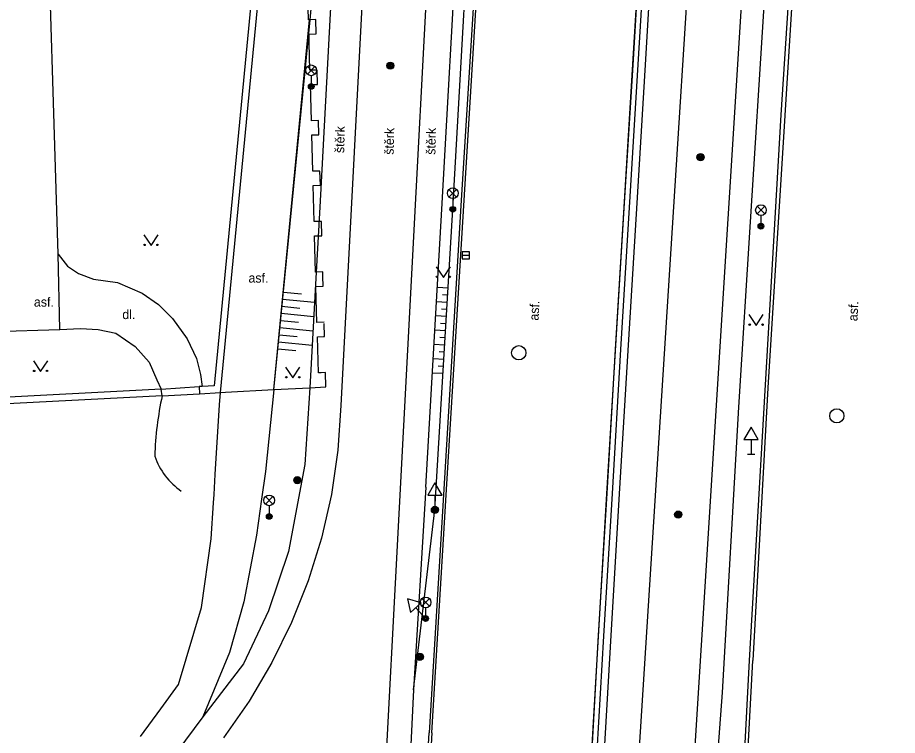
# Model space of a CAD drawing. Extents: x -599951 to -598963, y -1164095 to -1162939.
# Drawn here: x -599224.4 to -599162.9, y -1163976.7 to -1163926.5 of the extents above; entities that cross this region are included whole.
import ezdxf

# ---------------------------------------------------------------- set-up
doc = ezdxf.new("R2010")
doc.units = 0
for name, color, linetype in [('Level 1', 7, 'Continuous'), ('Level 10', 7, 'Continuous'), ('Level 11', 7, 'Continuous'), ('Level 13', 7, 'Continuous'), ('Level 14', 7, 'Continuous'), ('Level 15', 7, 'Continuous'), ('Level 25', 7, 'Continuous'), ('Level 27', 7, 'Continuous'), ('Level 33', 7, 'Continuous'), ('Level 34', 7, 'Continuous'), ('Level 36', 7, 'Continuous'), ('Level 40', 7, 'Continuous'), ('Level 54', 7, 'Continuous'), ('Level 7', 7, 'Continuous'), ('Level 8', 7, 'Continuous'), ('Level 9', 7, 'Continuous')]:
    doc.layers.add(name, color=color, linetype=linetype)

msp = doc.modelspace()

# ---------------------------------------------------------------- linework, layer by layer
at = {"layer": 'Level 1'}
for points in [[(-599203.06, -1163944.58), (-599203.07, -1163944.25), (-599203.57, -1163944.26), (-599203.64, -1163941.73), (-599203.14, -1163941.72), (-599203.17, -1163940.72), (-599203.67, -1163940.73), (-599203.74, -1163938.2), (-599203.24, -1163938.19), (-599203.27, -1163937.19), (-599203.77, -1163937.2), (-599203.84, -1163934.67), (-599203.34, -1163934.66), (-599203.37, -1163933.66), (-599203.87, -1163933.67), (-599203.94, -1163931.14), (-599203.44, -1163931.13), (-599203.47, -1163930.13), (-599203.97, -1163930.14), (-599204.02, -1163928.22), (-599204.02, -1163928.14), (-599204.03, -1163927.61), (-599203.53, -1163927.6), (-599203.56, -1163926.6), (-599204, -1163926.62), (-599204.06, -1163926.62), (-599204.13, -1163924.09)], [(-599203.06, -1163944.58), (-599203.07, -1163944.25), (-599203.57, -1163944.26), (-599203.64, -1163941.73), (-599203.14, -1163941.72), (-599203.17, -1163940.72), (-599203.67, -1163940.73), (-599203.74, -1163938.2), (-599203.24, -1163938.19), (-599203.27, -1163937.19), (-599203.77, -1163937.2), (-599203.84, -1163934.67), (-599203.34, -1163934.66), (-599203.37, -1163933.66), (-599203.87, -1163933.67), (-599203.94, -1163931.14), (-599203.44, -1163931.13), (-599203.47, -1163930.13), (-599203.97, -1163930.14), (-599204.02, -1163928.22), (-599204.02, -1163928.14), (-599204.03, -1163927.61), (-599203.53, -1163927.6), (-599203.56, -1163926.6), (-599204, -1163926.62), (-599204.06, -1163926.62), (-599204.13, -1163924.09)], [(-599202.97, -1163947.77), (-599202.98, -1163947.77), (-599203.48, -1163947.79), (-599203.55, -1163945.26), (-599203.05, -1163945.25), (-599203.06, -1163944.58)], [(-599202.97, -1163947.77), (-599202.98, -1163947.77), (-599203.48, -1163947.79), (-599203.55, -1163945.26), (-599203.05, -1163945.25), (-599203.06, -1163944.58)], [(-599210.23, -1163952.69), (-599209.89, -1163952.67), (-599206.5, -1163952.47), (-599203.97, -1163952.36), (-599203.23, -1163952.32), (-599202.85, -1163952.3), (-599202.88, -1163951.3), (-599203.18, -1163951.31), (-599203.38, -1163951.32), (-599203.45, -1163948.79), (-599203.03, -1163948.77), (-599202.95, -1163948.77), (-599202.98, -1163947.86)], [(-599210.23, -1163952.69), (-599209.89, -1163952.67), (-599206.5, -1163952.47), (-599203.97, -1163952.36), (-599203.23, -1163952.32), (-599202.85, -1163952.3), (-599202.88, -1163951.3), (-599203.18, -1163951.31), (-599203.38, -1163951.32), (-599203.45, -1163948.79), (-599203.03, -1163948.77), (-599202.95, -1163948.77), (-599202.98, -1163947.86)], [(-599214.31, -1163952.91), (-599211.69, -1163952.77)]]:
    msp.add_lwpolyline(points, dxfattribs=at)
at = {"layer": 'Level 10'}
for points in [[(-599162.85, -1163820.04), (-599165.66, -1163854.88), (-599168.46, -1163894.41), (-599171.02, -1163933.26), (-599173.23, -1163971.43)], [(-599162.85, -1163820.04), (-599165.66, -1163854.88), (-599168.46, -1163894.41), (-599171.02, -1163933.26), (-599173.23, -1163971.43)], [(-599189.93, -1163884.08), (-599190.81, -1163898.12), (-599192.15, -1163919.43), (-599193.42, -1163940)], [(-599193.42, -1163940), (-599194.6, -1163959.46), (-599195.62, -1163976.51)], [(-599173.23, -1163971.43), (-599174.29, -1163991.9), (-599175.35, -1164011.75), (-599176.55, -1164033.54), (-599177.56, -1164051.44), (-599178.64, -1164071.21)], [(-599196.92, -1163999.13), (-599195.62, -1163976.51)]]:
    msp.add_lwpolyline(points, dxfattribs=at)
at = {"layer": 'Level 11'}
for points in [[(-599172.9, -1163813.11), (-599173.38, -1163820.1), (-599174.07, -1163830.07), (-599174.74, -1163840.04), (-599175.4, -1163850), (-599175.95, -1163858.03), (-599176.47, -1163865.91), (-599177.1, -1163875.95), (-599177.75, -1163885.93), (-599178.52, -1163897.89), (-599179.3, -1163909.98), (-599179.92, -1163919.81), (-599180.51, -1163929.76), (-599181.12, -1163939.81), (-599181.72, -1163949.74), (-599182.32, -1163959.77), (-599182.91, -1163969.7), (-599183.49, -1163979.74), (-599184.17, -1163991.77), (-599185.17, -1164009.07), (-599185.26, -1164010.75)], [(-599172.9, -1163813.11), (-599173.38, -1163820.1), (-599174.07, -1163830.07), (-599174.74, -1163840.04), (-599175.4, -1163850), (-599175.95, -1163858.03), (-599176.47, -1163865.91), (-599177.1, -1163875.95), (-599177.75, -1163885.93), (-599178.52, -1163897.89), (-599179.3, -1163909.98), (-599179.92, -1163919.81), (-599180.51, -1163929.76), (-599181.12, -1163939.81), (-599181.72, -1163949.74), (-599182.32, -1163959.77), (-599182.91, -1163969.7), (-599183.49, -1163979.74), (-599184.17, -1163991.77), (-599185.17, -1164009.07), (-599185.26, -1164010.75)], [(-599197.62, -1163823.43), (-599198.25, -1163843.69), (-599199.2, -1163863.95), (-599200.91, -1163896.76), (-599202.16, -1163918.73), (-599203.28, -1163939.73), (-599203.53, -1163944.26), (-599203.97, -1163952.36)], [(-599197.62, -1163823.43), (-599198.25, -1163843.69), (-599199.2, -1163863.95), (-599200.91, -1163896.76), (-599202.16, -1163918.73), (-599203.28, -1163939.73), (-599203.53, -1163944.26), (-599203.97, -1163952.36)], [(-599195.85, -1163959.31), (-599194.73, -1163939.87), (-599193.59, -1163919.49), (-599192.41, -1163897.89), (-599191.62, -1163883.93)], [(-599168.22, -1163894.41), (-599169.52, -1163913.85), (-599170.73, -1163933.3)], [(-599193.23, -1163939.99), (-599191.96, -1163919.44), (-599190.62, -1163898.15)], [(-599171.48, -1163913.8), (-599172.21, -1163925.63), (-599173.16, -1163940.74), (-599173.97, -1163953.72)], [(-599186.16, -1164011.52), (-599186, -1164008.75), (-599185.03, -1163991.47), (-599184.35, -1163979.77), (-599183.76, -1163969.76), (-599183.18, -1163959.77), (-599182.58, -1163949.77), (-599181.98, -1163939.79), (-599181.35, -1163929.78), (-599180.76, -1163919.85), (-599180.56, -1163916.59)], [(-599206.5, -1163952.47), (-599204, -1163926.62)], [(-599170.73, -1163933.3), (-599171.92, -1163952.37), (-599172.98, -1163971.45)], [(-599195.43, -1163976.51), (-599194.4, -1163959.47), (-599193.23, -1163939.99)], [(-599221.47, -1163948.29), (-599221.59, -1163943.02)], [(-599221.59, -1163943.02), (-599220.94, -1163943.84), (-599220.17, -1163944.35), (-599219.12, -1163944.75), (-599217.44, -1163945), (-599215.7, -1163945.73), (-599214.57, -1163946.53), (-599213.59, -1163947.51), (-599212.57, -1163948.93), (-599211.91, -1163950.32), (-599211.62, -1163951.44), (-599211.51, -1163952.26)], [(-599221.47, -1163948.29), (-599220.03, -1163948.2), (-599218.79, -1163948.28), (-599217.55, -1163948.53), (-599216.21, -1163949.48), (-599215.22, -1163950.57), (-599214.68, -1163951.81), (-599214.37, -1163952.46)], [(-599226.09, -1163948.43), (-599221.47, -1163948.29)], [(-599203.97, -1163952.36), (-599204.33, -1163957.73), (-599205.47, -1163963.81), (-599206.88, -1163967.96), (-599208.62, -1163971.68), (-599211.47, -1163975.39)], [(-599203.97, -1163952.36), (-599204.33, -1163957.73), (-599205.47, -1163963.81), (-599206.88, -1163967.96), (-599208.62, -1163971.68), (-599211.47, -1163975.39)], [(-599206.5, -1163952.47), (-599206.5, -1163952.5), (-599207.07, -1163958.22), (-599207.35, -1163960.16), (-599207.71, -1163962.67), (-599208.59, -1163967.34), (-599209.61, -1163970.87), (-599211.47, -1163975.39)], [(-599206.5, -1163952.47), (-599206.5, -1163952.5), (-599207.07, -1163958.22), (-599207.35, -1163960.16), (-599207.71, -1163962.67), (-599208.59, -1163967.34), (-599209.61, -1163970.87), (-599211.47, -1163975.39)], [(-599215.82, -1163976.75), (-599214.4, -1163974.81), (-599213.16, -1163973.11), (-599211.56, -1163967.72), (-599210.88, -1163962.93), (-599210.72, -1163960.41), (-599210.68, -1163959.83), (-599210.59, -1163958.43), (-599210.29, -1163953.56), (-599210.23, -1163952.69)], [(-599215.82, -1163976.75), (-599214.4, -1163974.81), (-599213.16, -1163973.11), (-599211.56, -1163967.72), (-599210.88, -1163962.93), (-599210.72, -1163960.41), (-599210.68, -1163959.83), (-599210.59, -1163958.43), (-599210.29, -1163953.56), (-599210.23, -1163952.69)], [(-599173.97, -1163953.72), (-599175.11, -1163973.69), (-599176.62, -1163993.64)], [(-599195.85, -1163959.31), (-599196.72, -1163973.49)], [(-599178.38, -1164071.18), (-599177.31, -1164051.48), (-599176.3, -1164033.6), (-599175.12, -1164011.76), (-599174.06, -1163991.91), (-599172.98, -1163971.45)], [(-599196.72, -1163973.49), (-599197.56, -1163990.8), (-599198.17, -1163999.99)], [(-599211.47, -1163975.39), (-599216.86, -1163982.64), (-599230.24, -1164000.07), (-599257.58, -1164035.67), (-599261.16, -1164041.12), (-599262.87, -1164045.41), (-599264.04, -1164049.93), (-599264.28, -1164054.68), (-599263.81, -1164059.27), (-599262.56, -1164063.71), (-599259.99, -1164068.39), (-599256.72, -1164072.83), (-599254.73, -1164074.44)], [(-599195.43, -1163976.51), (-599196.69, -1163998.47)]]:
    msp.add_lwpolyline(points, dxfattribs=at)
for centre, radius, start, end in [((-599191.338, -1163957.881), 23.503, 167.7899, 178.19352), ((-599210.143, -1163955.513), 4.961, 199.14564, 235.26471)]:
    msp.add_arc(centre, radius, start, end, dxfattribs=at)
at = {"layer": 'Level 13'}
for points in [[(-599178.43, -1164000.2), (-599167.24, -1163821.2)], [(-599173.6, -1163862.17), (-599182.35, -1163999.95)], [(-599193.21, -1163875.57), (-599199.31, -1163990.76)], [(-599199.93, -1163918.11), (-599201.8, -1163953.59)], [(-599201.8, -1163953.59), (-599202.01, -1163956.72), (-599202.47, -1163959.82), (-599203.16, -1163962.87), (-599204.09, -1163965.87), (-599205.25, -1163968.78), (-599206.63, -1163971.59), (-599208.22, -1163974.29), (-599210.02, -1163976.85)]]:
    msp.add_lwpolyline(points, dxfattribs=at)
at = {"layer": 'Level 14'}
msp.add_lwpolyline([(-599196.72, -1163973.49), (-599195.22, -1163960.9), (-599193.97, -1163939.87), (-599192.41, -1163912.27), (-599190.93, -1163884.04)], dxfattribs=at)
at = {"layer": 'Level 15'}
for points in [[(-599204.57, -1163945.8), (-599205.83, -1163945.68)], [(-599194.3, -1163945.38), (-599195.04, -1163945.34)], [(-599203.65, -1163946.4), (-599205.88, -1163946.18)], [(-599194.36, -1163946.38), (-599195.1, -1163946.34)], [(-599194.33, -1163945.88), (-599194.7, -1163945.86)], [(-599204.67, -1163946.8), (-599205.93, -1163946.68)], [(-599194.39, -1163946.88), (-599194.76, -1163946.86)], [(-599203.7, -1163947.4), (-599205.98, -1163947.17)], [(-599194.42, -1163947.38), (-599195.16, -1163947.33)], [(-599203.76, -1163948.4), (-599206.07, -1163948.17)], [(-599204.77, -1163947.79), (-599206.03, -1163947.67)], [(-599194.45, -1163947.88), (-599194.82, -1163947.85)], [(-599204.87, -1163948.79), (-599206.12, -1163948.67)], [(-599194.48, -1163948.38), (-599195.22, -1163948.33)], [(-599194.51, -1163948.87), (-599194.88, -1163948.85)], [(-599203.81, -1163949.39), (-599206.17, -1163949.16)], [(-599194.54, -1163949.37), (-599195.27, -1163949.33)], [(-599204.96, -1163949.78), (-599206.22, -1163949.66)], [(-599194.56, -1163949.87), (-599194.93, -1163949.85)], [(-599194.6, -1163950.37), (-599195.33, -1163950.33)], [(-599194.65, -1163951.37), (-599195.39, -1163951.33)], [(-599194.62, -1163950.87), (-599194.99, -1163950.85)]]:
    msp.add_lwpolyline(points, dxfattribs=at)
at = {"layer": 'Level 25'}
for centre, radius in [((-599198.34, -1163929.82), 0.25), ((-599198.34, -1163929.82), 0.2), ((-599198.34, -1163929.82), 0.15), ((-599198.34, -1163929.82), 0.1), ((-599198.34, -1163929.82), 0.05), ((-599176.63, -1163936.22), 0.25), ((-599176.63, -1163936.22), 0.2), ((-599176.63, -1163936.22), 0.15), ((-599176.63, -1163936.22), 0.1), ((-599176.63, -1163936.22), 0.05), ((-599204.85, -1163958.82), 0.25), ((-599204.85, -1163958.82), 0.2), ((-599204.85, -1163958.82), 0.15), ((-599204.85, -1163958.82), 0.1), ((-599204.85, -1163958.82), 0.05), ((-599195.22, -1163960.9), 0.25), ((-599195.22, -1163960.9), 0.2), ((-599195.22, -1163960.9), 0.15), ((-599195.22, -1163960.9), 0.1), ((-599195.22, -1163960.9), 0.05), ((-599178.19, -1163961.23), 0.25), ((-599178.19, -1163961.23), 0.2), ((-599178.19, -1163961.23), 0.15), ((-599178.19, -1163961.23), 0.1), ((-599178.19, -1163961.23), 0.05), ((-599196.27, -1163971.18), 0.25), ((-599196.27, -1163971.18), 0.2), ((-599196.27, -1163971.18), 0.15), ((-599196.27, -1163971.18), 0.1), ((-599196.27, -1163971.18), 0.05)]:
    msp.add_circle(centre, radius, dxfattribs=at)
at = {"layer": 'Level 27'}
msp.add_line((-599193.31, -1163943.09), (-599192.81, -1163943.09), dxfattribs=at)
msp.add_lwpolyline([(-599193.31, -1163943.34), (-599192.81, -1163943.34), (-599192.81, -1163942.84), (-599193.31, -1163942.84)], close=True, dxfattribs=at)
for centre in [(-599189.35, -1163949.91), (-599167.09, -1163954.32)]:
    msp.add_circle(centre, 0.5, dxfattribs=at)
at = {"layer": 'Level 33'}
for p, q in [((-599204.145, -1163930.41), (-599203.615, -1163929.88)), ((-599204.145, -1163929.88), (-599203.615, -1163930.41)), ((-599203.88, -1163930.52), (-599203.88, -1163931.27)), ((-599194.235, -1163939.01), (-599193.705, -1163938.48)), ((-599194.235, -1163938.48), (-599193.705, -1163939.01)), ((-599193.97, -1163939.12), (-599193.97, -1163939.87)), ((-599172.665, -1163940.19), (-599172.135, -1163939.66)), ((-599172.665, -1163939.66), (-599172.135, -1163940.19)), ((-599172.4, -1163940.3), (-599172.4, -1163941.05)), ((-599207.085, -1163960.5), (-599206.555, -1163959.97)), ((-599207.085, -1163959.97), (-599206.555, -1163960.5)), ((-599206.82, -1163960.61), (-599206.82, -1163961.36)), ((-599196.135, -1163967.64), (-599195.605, -1163967.11)), ((-599196.135, -1163967.11), (-599195.605, -1163967.64)), ((-599195.87, -1163967.75), (-599195.87, -1163968.5))]:
    msp.add_line(p, q, dxfattribs=at)
for centre, radius in [((-599203.88, -1163930.145), 0.375), ((-599203.88, -1163931.27), 0.2), ((-599203.88, -1163931.27), 0.145), ((-599203.88, -1163931.27), 0.0876), ((-599193.97, -1163938.745), 0.375), ((-599172.4, -1163939.925), 0.375), ((-599193.97, -1163939.87), 0.2), ((-599193.97, -1163939.87), 0.145), ((-599193.97, -1163939.87), 0.0876), ((-599172.4, -1163941.05), 0.2), ((-599172.4, -1163941.05), 0.145), ((-599172.4, -1163941.05), 0.0876), ((-599206.82, -1163960.235), 0.375), ((-599206.82, -1163961.36), 0.2), ((-599206.82, -1163961.36), 0.145), ((-599206.82, -1163961.36), 0.0876), ((-599195.87, -1163967.375), 0.375), ((-599195.87, -1163968.5), 0.2), ((-599195.87, -1163968.5), 0.145), ((-599195.87, -1163968.5), 0.0876)]:
    msp.add_circle(centre, radius, dxfattribs=at)
at = {"layer": 'Level 34'}
for p, q in [((-599173.09, -1163955.982), (-599173.09, -1163957)), ((-599173.34, -1163957), (-599172.84, -1163957)), ((-599195.22, -1163959.882), (-599195.22, -1163960.9)), ((-599195.47, -1163960.9), (-599194.97, -1163960.9)), ((-599196.56, -1163967.752), (-599195.87, -1163968.5))]:
    msp.add_line(p, q, dxfattribs=at)
for points in [[(-599173.59, -1163955.982), (-599172.59, -1163955.982), (-599173.09, -1163955.116)], [(-599195.72, -1163959.882), (-599194.72, -1163959.882), (-599195.22, -1163959.016)], [(-599196.928, -1163968.091), (-599196.193, -1163967.413), (-599197.148, -1163967.116)]]:
    msp.add_lwpolyline(points, close=True, dxfattribs=at)
at = {"layer": 'Level 36'}
for points in [[(-599215.59, -1163941.66), (-599215.09, -1163942.41), (-599214.59, -1163941.66)], [(-599195.13, -1163943.89), (-599194.63, -1163944.64), (-599194.13, -1163943.89)], [(-599173.24, -1163947.24), (-599172.74, -1163947.99), (-599172.24, -1163947.24)], [(-599223.32, -1163950.48), (-599222.82, -1163951.23), (-599222.32, -1163950.48)], [(-599205.67, -1163950.92), (-599205.17, -1163951.67), (-599204.67, -1163950.92)]]:
    msp.add_lwpolyline(points, dxfattribs=at)
for centre in [(-599215.54, -1163942.36), (-599214.641, -1163942.36), (-599195.08, -1163944.59), (-599194.181, -1163944.59), (-599173.19, -1163947.94), (-599172.291, -1163947.94), (-599223.27, -1163951.18), (-599222.371, -1163951.18), (-599205.62, -1163951.62), (-599204.721, -1163951.62)]:
    msp.add_circle(centre, 0.05, dxfattribs=at)
at = {"layer": 'Level 54'}
msp.add_lwpolyline([(-599221.59, -1163943.02), (-599223.32, -1163886.92)], dxfattribs=at)
at = {"layer": 'Level 7'}
for points in [[(-599205.38, -1163897.08), (-599210.68, -1163952.21), (-599211.51, -1163952.26)], [(-599210.23, -1163952.69), (-599204.88, -1163897.13)], [(-599210.23, -1163952.69), (-599204.88, -1163897.13)], [(-599214.37, -1163952.46), (-599227.28, -1163953.12)], [(-599214.31, -1163952.91), (-599214.37, -1163952.46)], [(-599214.31, -1163952.91), (-599214.37, -1163952.46)], [(-599211.51, -1163952.26), (-599211.71, -1163952.27)], [(-599211.71, -1163952.27), (-599211.69, -1163952.77)], [(-599211.71, -1163952.27), (-599211.69, -1163952.77)], [(-599214.31, -1163952.91), (-599227.43, -1163953.6)], [(-599214.31, -1163952.91), (-599227.43, -1163953.6)], [(-599211.69, -1163952.77), (-599210.23, -1163952.69)], [(-599211.69, -1163952.77), (-599210.23, -1163952.69)]]:
    msp.add_lwpolyline(points, dxfattribs=at)
at = {"layer": 'Level 8'}
msp.add_lwpolyline([(-599214.37, -1163952.46), (-599211.71, -1163952.27)], dxfattribs=at)
at = {"layer": 'Level 9'}
for points in [[(-599173.33, -1163813.06), (-599173.85, -1163820.02), (-599174.57, -1163830.04), (-599175.22, -1163839.98), (-599175.88, -1163849.93), (-599176.42, -1163857.97), (-599177.03, -1163867.36), (-599177.61, -1163875.9), (-599178.24, -1163885.85), (-599178.98, -1163897.83), (-599179.77, -1163909.83), (-599180.41, -1163919.76), (-599181.02, -1163929.73), (-599181.63, -1163939.74), (-599182.23, -1163949.69), (-599182.82, -1163959.75), (-599183.42, -1163969.73), (-599184.01, -1163979.76), (-599184.69, -1163991.72), (-599185.65, -1164008.82), (-599186.25, -1164019.31), (-599186.77, -1164028.71), (-599187.18, -1164036.5)], [(-599173.33, -1163813.06), (-599173.85, -1163820.02), (-599174.57, -1163830.04), (-599175.22, -1163839.98), (-599175.88, -1163849.93), (-599176.42, -1163857.97), (-599177.03, -1163867.36), (-599177.61, -1163875.9), (-599178.24, -1163885.85), (-599178.98, -1163897.83), (-599179.77, -1163909.83), (-599180.41, -1163919.76), (-599181.02, -1163929.73), (-599181.63, -1163939.74), (-599182.23, -1163949.69), (-599182.82, -1163959.75), (-599183.42, -1163969.73), (-599184.01, -1163979.76), (-599184.69, -1163991.72), (-599185.65, -1164008.82), (-599186.25, -1164019.31), (-599186.77, -1164028.71), (-599187.18, -1164036.5)], [(-599206.5, -1163952.5), (-599203.95, -1163926.62), (-599203.22, -1163918.71), (-599201.28, -1163896.56), (-599201.86, -1163877.48)], [(-599206.5, -1163952.5), (-599203.95, -1163926.62), (-599203.22, -1163918.71), (-599201.28, -1163896.56), (-599201.86, -1163877.48)], [(-599180.61, -1163916.55), (-599180.74, -1163919.06), (-599181.39, -1163929.71), (-599182, -1163939.72), (-599182.6, -1163949.67), (-599183.19, -1163959.73), (-599183.79, -1163969.7), (-599184.36, -1163979.74), (-599185.06, -1163991.7), (-599186.02, -1164008.8), (-599186.16, -1164011.52)]]:
    msp.add_lwpolyline(points, dxfattribs=at)

# ---------------------------------------------------------------- texts
at = {"layer": 'Level 40'}
for s, rotation, p in [('štěrk', 88.75, (-599201.57, -1163935.94)), ('štěrk', 88.75, (-599198.11, -1163936.06)), ('štěrk', 88.75, (-599195.19, -1163936.06)), ('asf.', 87.1, (-599187.97, -1163947.67)), ('asf.', 87.1, (-599165.65, -1163947.71))]:
    msp.add_text(s, height=0.65, rotation=rotation, dxfattribs=at).set_placement(p)
for s, p in [('asf.', (-599208.27, -1163945)), ('asf.', (-599223.29, -1163946.68)), ('dl.', (-599217.1, -1163947.55))]:
    msp.add_text(s, height=0.65, dxfattribs=at).set_placement(p)

doc.saveas('drawing.dxf')
